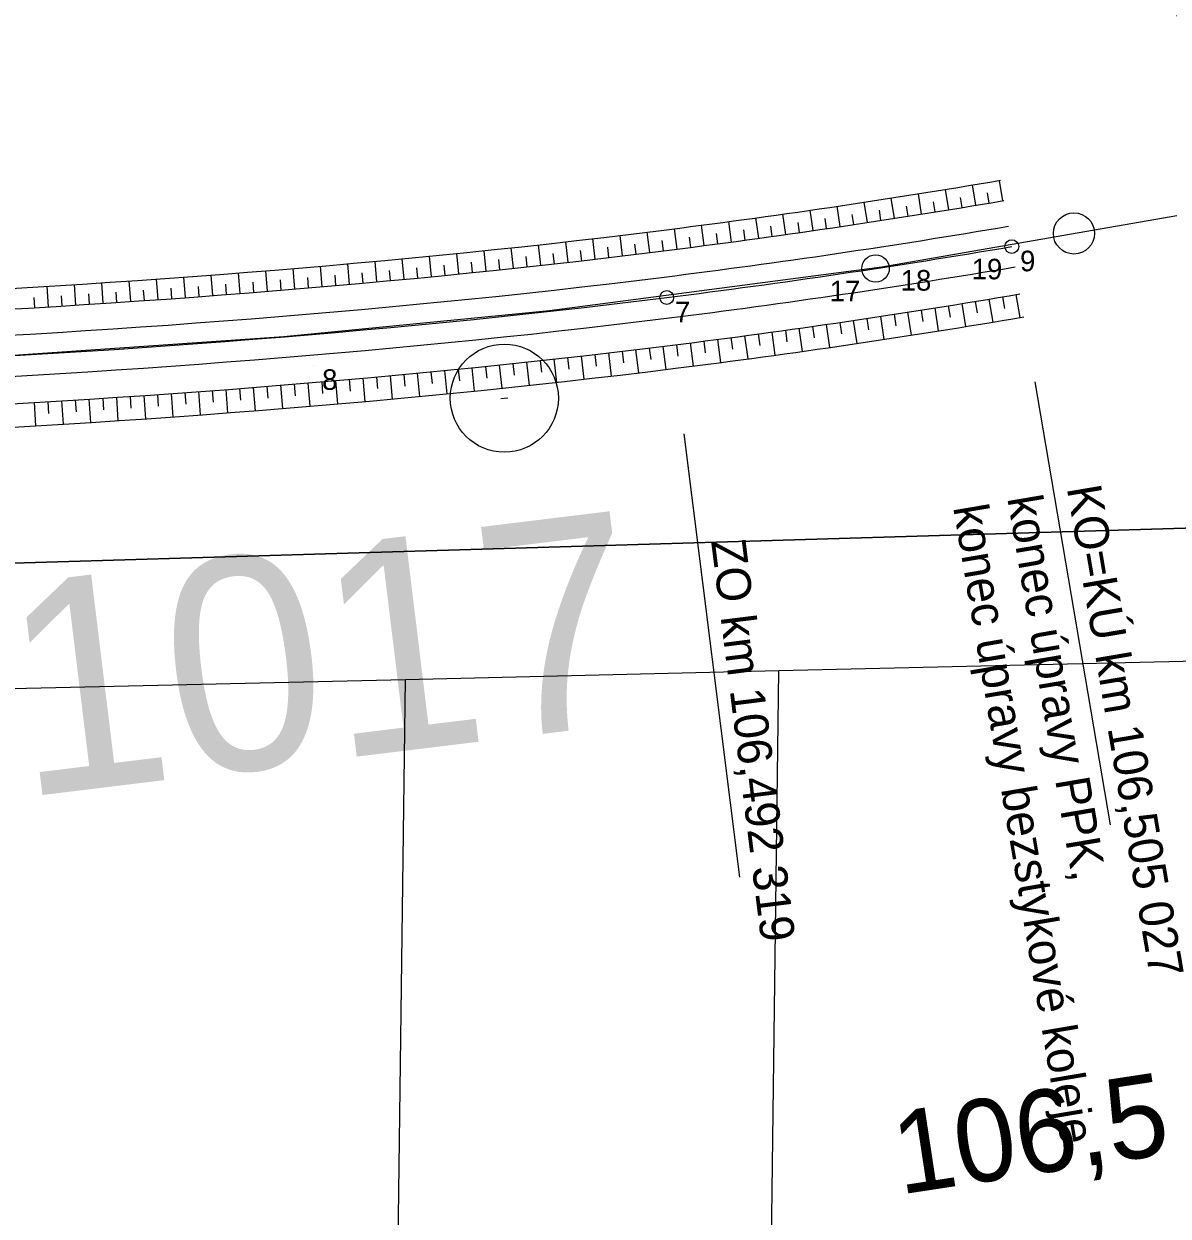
# Model space of a CAD drawing. Extents: x -758836 to -757729, y -1175316 to -1174366.
# Drawn here: x -758139.87 to -758098.18, y -1174793.97 to -1174750.54 of the extents above; entities that cross this region are included whole.
import ezdxf

# ---------------------------------------------------------------- set-up
doc = ezdxf.new("R2010")
doc.units = 0
for name, color, linetype in [('_NOR-návrh tenká', 7, 'Continuous'), ('_NOR-osa', 7, 'Continuous'), ('_NOR-popis', 7, 'Continuous'), ('_NOR-svahy', 7, 'Continuous'), ('_NOR-vytyčení', 7, 'Continuous'), ('G_Obvod stavby', 7, 'Continuous'), ('Hranice parcel', 7, 'Continuous'), ('Vrstva 1', 7, 'Continuous'), ('Vrstva 63', 7, 'Continuous'), ('Vrstva 7', 7, 'Continuous')]:
    doc.layers.add(name, color=color, linetype=linetype)

# ---------------------------------------------------------------- blocks, each defined once
blk = doc.blocks.new('C513_1')
at = {"layer": 'Vrstva 7'}
blk.add_circle((0, 0), 0.75, dxfattribs=at)
blk = doc.blocks.new('POINT_DISPLAY')
blk.add_line((0, 0), (0, 0))
blk = doc.blocks.new('C015_1')
at = {"layer": 'Vrstva 63'}
blk.add_line((-0.05, 0), (0.05, 0), dxfattribs=at)
blk.add_circle((0, 0), 0.756, dxfattribs=at)

msp = doc.modelspace()

# ---------------------------------------------------------------- linework, layer by layer
at = {"layer": '_NOR-návrh tenká'}
for points in [[(-758140.749, -1174760.203), (-758139.746, -1174760.144), (-758138.742, -1174760.083), (-758137.739, -1174760.02), (-758136.736, -1174759.955), (-758135.733, -1174759.887), (-758134.731, -1174759.816), (-758133.729, -1174759.744), (-758132.727, -1174759.669), (-758131.726, -1174759.591), (-758130.725, -1174759.51), (-758129.724, -1174759.427), (-758128.724, -1174759.341), (-758127.724, -1174759.253), (-758126.724, -1174759.161), (-758125.725, -1174759.067), (-758124.727, -1174758.97), (-758123.728, -1174758.869), (-758122.731, -1174758.766), (-758121.733, -1174758.66), (-758120.736, -1174758.55), (-758119.74, -1174758.437), (-758118.744, -1174758.321), (-758117.749, -1174758.201), (-758116.752, -1174758.078)], [(-758140.706, -1174760.952), (-758139.701, -1174760.893), (-758138.696, -1174760.832), (-758137.691, -1174760.768), (-758136.686, -1174760.703), (-758135.682, -1174760.635), (-758134.678, -1174760.565), (-758133.674, -1174760.492), (-758132.67, -1174760.416), (-758131.667, -1174760.338), (-758130.664, -1174760.258), (-758129.661, -1174760.175), (-758128.659, -1174760.089), (-758127.657, -1174760), (-758126.655, -1174759.908), (-758125.654, -1174759.814), (-758124.653, -1174759.716), (-758123.652, -1174759.616), (-758122.652, -1174759.512), (-758121.652, -1174759.405), (-758120.653, -1174759.295), (-758119.654, -1174759.182), (-758118.656, -1174759.066), (-758117.658, -1174758.946), (-758116.659, -1174758.823)], [(-758140.652, -1174761.9), (-758139.644, -1174761.841), (-758138.637, -1174761.78), (-758137.63, -1174761.716), (-758136.623, -1174761.651), (-758135.616, -1174761.583), (-758134.61, -1174761.512), (-758133.604, -1174761.439), (-758132.598, -1174761.364), (-758131.592, -1174761.285), (-758130.586, -1174761.205), (-758129.581, -1174761.121), (-758128.576, -1174761.035), (-758127.571, -1174760.946), (-758126.567, -1174760.854), (-758125.563, -1174760.759), (-758124.559, -1174760.661), (-758123.556, -1174760.561), (-758122.553, -1174760.457), (-758121.55, -1174760.35), (-758120.548, -1174760.239), (-758119.546, -1174760.126), (-758118.544, -1174760.009), (-758117.543, -1174759.889), (-758116.542, -1174759.765)], [(-758140.566, -1174763.398), (-758139.555, -1174763.338), (-758138.544, -1174763.277), (-758137.534, -1174763.213), (-758136.524, -1174763.147), (-758135.513, -1174763.079), (-758134.503, -1174763.008), (-758133.493, -1174762.935), (-758132.483, -1174762.859), (-758131.474, -1174762.781), (-758130.464, -1174762.7), (-758129.455, -1174762.616), (-758128.446, -1174762.529), (-758127.437, -1174762.44), (-758126.428, -1174762.348), (-758125.42, -1174762.252), (-758124.411, -1174762.154), (-758123.404, -1174762.053), (-758122.396, -1174761.949), (-758121.388, -1174761.841), (-758120.381, -1174761.73), (-758119.375, -1174761.616), (-758118.368, -1174761.499), (-758117.362, -1174761.378), (-758116.357, -1174761.254)], [(-758140.508, -1174764.396), (-758139.496, -1174764.337), (-758138.483, -1174764.275), (-758137.47, -1174764.211), (-758136.457, -1174764.145), (-758135.445, -1174764.077), (-758134.432, -1174764.006), (-758133.42, -1174763.932), (-758132.407, -1174763.856), (-758131.395, -1174763.778), (-758130.383, -1174763.696), (-758129.371, -1174763.612), (-758128.359, -1174763.526), (-758127.347, -1174763.436), (-758126.336, -1174763.343), (-758125.324, -1174763.248), (-758124.313, -1174763.149), (-758123.302, -1174763.048), (-758122.291, -1174762.943), (-758121.281, -1174762.835), (-758120.27, -1174762.724), (-758119.26, -1174762.61), (-758118.251, -1174762.492), (-758117.241, -1174762.371), (-758116.233, -1174762.246)], [(-758140.46, -1174765.245), (-758139.445, -1174765.185), (-758138.43, -1174765.124), (-758137.416, -1174765.06), (-758136.401, -1174764.993), (-758135.386, -1174764.925), (-758134.372, -1174764.854), (-758133.357, -1174764.78), (-758132.343, -1174764.704), (-758131.328, -1174764.625), (-758130.314, -1174764.544), (-758129.299, -1174764.459), (-758128.285, -1174764.372), (-758127.271, -1174764.283), (-758126.257, -1174764.19), (-758125.243, -1174764.094), (-758124.229, -1174763.995), (-758123.216, -1174763.893), (-758122.202, -1174763.788), (-758121.189, -1174763.68), (-758120.176, -1174763.569), (-758119.163, -1174763.454), (-758118.151, -1174763.336), (-758117.138, -1174763.214), (-758116.129, -1174763.09)]]:
    msp.add_lwpolyline(points, dxfattribs=at)
for radius, start in [(288.55, 277.14072), (289.3, 277.14059), (290.25, 277.14043), (291.75, 277.14018), (292.75, 277.14001), (293.6, 277.13986)]:
    msp.add_arc((-758152.621, -1174471.766), radius, start, 279.64253, dxfattribs=at)
at = {"layer": '_NOR-osa'}
msp.add_lwpolyline([(-758140.609, -1174762.649), (-758139.6, -1174762.59), (-758138.591, -1174762.528), (-758137.582, -1174762.465), (-758136.573, -1174762.399), (-758135.565, -1174762.331), (-758134.557, -1174762.26), (-758133.549, -1174762.187), (-758132.541, -1174762.111), (-758131.533, -1174762.033), (-758130.525, -1174761.952), (-758129.518, -1174761.869), (-758128.511, -1174761.782), (-758127.504, -1174761.693), (-758126.498, -1174761.601), (-758125.491, -1174761.506), (-758124.485, -1174761.408), (-758123.48, -1174761.307), (-758122.474, -1174761.203), (-758121.469, -1174761.095), (-758120.465, -1174760.985), (-758119.46, -1174760.871), (-758118.456, -1174760.754), (-758117.453, -1174760.633), (-758116.45, -1174760.51)], dxfattribs=at)
for centre in [(-758103.878, -1174758.655), (-758116.45, -1174760.51)]:
    msp.add_circle(centre, 0.25, dxfattribs=at)
msp.add_arc((-758152.621, -1174471.766), 291, 277.1403, 279.64253, dxfattribs=at)
at = {"layer": '_NOR-popis'}
for p, q in [((-758103.04, -1174763.584), (-758100.3, -1174779.715)), ((-758115.828, -1174765.471), (-758113.804, -1174781.63))]:
    msp.add_line(p, q, dxfattribs=at)
msp.add_circle((-758108.841, -1174759.454), 0.5, dxfattribs=at)
at = {"layer": '_NOR-svahy'}
for points in [[(-758105.19, -1174757.152), (-758105.313, -1174756.412)], [(-758104.204, -1174756.986), (-758104.33, -1174756.247)], [(-758108.152, -1174757.628), (-758108.268, -1174756.887)], [(-758107.164, -1174757.473), (-758107.282, -1174756.732)], [(-758106.177, -1174757.314), (-758106.298, -1174756.574)], [(-758105.684, -1174757.233), (-758105.745, -1174756.863)], [(-758104.697, -1174757.069), (-758104.759, -1174756.7)], [(-758111.119, -1174758.074), (-758111.227, -1174757.332)], [(-758110.13, -1174757.929), (-758110.24, -1174757.187)], [(-758109.141, -1174757.78), (-758109.253, -1174757.039)], [(-758108.646, -1174757.705), (-758108.703, -1174757.334)], [(-758107.658, -1174757.551), (-758107.717, -1174757.181)], [(-758106.671, -1174757.394), (-758106.73, -1174757.024)], [(-758114.09, -1174758.489), (-758114.19, -1174757.746)], [(-758113.099, -1174758.354), (-758113.202, -1174757.611)], [(-758112.109, -1174758.216), (-758112.214, -1174757.473)], [(-758111.614, -1174758.145), (-758111.667, -1174757.774)], [(-758110.624, -1174758.002), (-758110.679, -1174757.631)], [(-758109.635, -1174757.855), (-758109.691, -1174757.484)], [(-758117.066, -1174758.873), (-758117.157, -1174758.128)], [(-758116.073, -1174758.749), (-758116.168, -1174758.005)], [(-758115.081, -1174758.62), (-758115.179, -1174757.877)], [(-758114.586, -1174758.555), (-758114.635, -1174758.183)], [(-758113.595, -1174758.422), (-758113.645, -1174758.05)], [(-758112.604, -1174758.285), (-758112.656, -1174757.914)], [(-758121.038, -1174759.338), (-758121.12, -1174758.592)], [(-758120.045, -1174759.226), (-758120.129, -1174758.481)], [(-758119.051, -1174759.112), (-758119.138, -1174758.367)], [(-758118.058, -1174758.994), (-758118.148, -1174758.249)], [(-758117.562, -1174758.934), (-758117.608, -1174758.562)], [(-758116.569, -1174758.811), (-758116.616, -1174758.439)], [(-758115.577, -1174758.685), (-758115.625, -1174758.313)], [(-758126.012, -1174759.847), (-758126.083, -1174759.101)], [(-758125.017, -1174759.752), (-758125.09, -1174759.005)], [(-758124.022, -1174759.653), (-758124.097, -1174758.906)], [(-758123.027, -1174759.551), (-758123.104, -1174758.805)], [(-758122.033, -1174759.446), (-758122.112, -1174758.7)], [(-758121.535, -1174759.392), (-758121.576, -1174759.02)], [(-758120.541, -1174759.283), (-758120.584, -1174758.91)], [(-758119.548, -1174759.17), (-758119.591, -1174758.797)], [(-758118.555, -1174759.054), (-758118.599, -1174758.681)], [(-758130.993, -1174760.284), (-758131.053, -1174759.537)], [(-758129.996, -1174760.202), (-758130.059, -1174759.455)], [(-758129, -1174760.118), (-758129.064, -1174759.371)], [(-758128.004, -1174760.031), (-758128.07, -1174759.284)], [(-758127.008, -1174759.94), (-758127.076, -1174759.194)], [(-758126.51, -1174759.894), (-758126.545, -1174759.521)], [(-758125.515, -1174759.8), (-758125.551, -1174759.427)], [(-758124.519, -1174759.703), (-758124.557, -1174759.33)], [(-758123.524, -1174759.602), (-758123.563, -1174759.229)], [(-758122.53, -1174759.499), (-758122.569, -1174759.126)], [(-758136.977, -1174760.722), (-758137.026, -1174759.973)], [(-758135.979, -1174760.655), (-758136.03, -1174759.907)], [(-758134.982, -1174760.586), (-758135.034, -1174759.838)], [(-758133.984, -1174760.514), (-758134.039, -1174759.766)], [(-758132.987, -1174760.44), (-758133.043, -1174759.692)], [(-758131.99, -1174760.364), (-758132.048, -1174759.616)], [(-758131.491, -1174760.324), (-758131.522, -1174759.951)], [(-758130.495, -1174760.244), (-758130.526, -1174759.87)], [(-758129.498, -1174760.161), (-758129.53, -1174759.787)], [(-758128.502, -1174760.075), (-758128.535, -1174759.701)], [(-758127.506, -1174759.986), (-758127.54, -1174759.613)], [(-758138.973, -1174760.849), (-758139.018, -1174760.1)], [(-758137.975, -1174760.786), (-758138.022, -1174760.038)], [(-758137.476, -1174760.754), (-758137.5, -1174760.38)], [(-758136.478, -1174760.689), (-758136.503, -1174760.315)], [(-758135.48, -1174760.621), (-758135.507, -1174760.247)], [(-758134.483, -1174760.55), (-758134.51, -1174760.176)], [(-758133.486, -1174760.478), (-758133.514, -1174760.104)], [(-758132.488, -1174760.402), (-758132.517, -1174760.028)], [(-758103.728, -1174760.405), (-758103.586, -1174761.243)], [(-758139.472, -1174760.879), (-758139.495, -1174760.505)], [(-758138.474, -1174760.818), (-758138.498, -1174760.444)], [(-758106.194, -1174760.812), (-758106.127, -1174761.231)], [(-758105.701, -1174760.732), (-758105.564, -1174761.571)], [(-758105.207, -1174760.651), (-758105.138, -1174761.071)], [(-758104.714, -1174760.57), (-758104.575, -1174761.408)], [(-758104.221, -1174760.488), (-758104.15, -1174760.907)], [(-758109.159, -1174761.272), (-758109.096, -1174761.692)], [(-758108.664, -1174761.197), (-758108.537, -1174762.038)], [(-758108.17, -1174761.122), (-758108.106, -1174761.542)], [(-758107.676, -1174761.046), (-758107.545, -1174761.886)], [(-758107.182, -1174760.968), (-758107.116, -1174761.388)], [(-758106.688, -1174760.89), (-758106.555, -1174761.73)], [(-758112.128, -1174761.702), (-758112.069, -1174762.123)], [(-758111.633, -1174761.633), (-758111.514, -1174762.474)], [(-758111.138, -1174761.562), (-758111.077, -1174761.983)], [(-758110.643, -1174761.491), (-758110.521, -1174762.332)], [(-758110.148, -1174761.419), (-758110.086, -1174761.839)], [(-758109.653, -1174761.346), (-758109.528, -1174762.187)], [(-758115.101, -1174762.102), (-758115.046, -1174762.524)], [(-758114.605, -1174762.038), (-758114.495, -1174762.88)], [(-758114.109, -1174761.972), (-758114.053, -1174762.393)], [(-758113.614, -1174761.906), (-758113.501, -1174762.748)], [(-758113.118, -1174761.839), (-758113.061, -1174762.26)], [(-758112.623, -1174761.771), (-758112.507, -1174762.613)], [(-758118.575, -1174762.53), (-758118.476, -1174763.374)], [(-758118.078, -1174762.471), (-758118.027, -1174762.893)], [(-758117.582, -1174762.411), (-758117.48, -1174763.255)], [(-758117.085, -1174762.351), (-758117.033, -1174762.773)], [(-758116.589, -1174762.29), (-758116.485, -1174763.134)], [(-758116.093, -1174762.229), (-758116.04, -1174762.65)], [(-758115.597, -1174762.166), (-758115.489, -1174763.009)], [(-758122.55, -1174762.97), (-758122.463, -1174763.815)], [(-758122.053, -1174762.918), (-758122.008, -1174763.34)], [(-758121.556, -1174762.865), (-758121.466, -1174763.71)], [(-758121.059, -1174762.811), (-758121.012, -1174763.233)], [(-758120.562, -1174762.756), (-758120.469, -1174763.601)], [(-758120.065, -1174762.701), (-758120.017, -1174763.123)], [(-758119.568, -1174762.644), (-758119.472, -1174763.489)], [(-758119.071, -1174762.588), (-758119.022, -1174763.01)], [(-758127.527, -1174763.452), (-758127.452, -1174764.299)], [(-758127.029, -1174763.407), (-758126.99, -1174763.83)], [(-758126.531, -1174763.361), (-758126.454, -1174764.208)], [(-758126.033, -1174763.315), (-758125.993, -1174763.738)], [(-758125.536, -1174763.268), (-758125.456, -1174764.114)], [(-758125.038, -1174763.22), (-758124.997, -1174763.643)], [(-758124.54, -1174763.171), (-758124.458, -1174764.017)], [(-758124.043, -1174763.122), (-758124, -1174763.545)], [(-758123.545, -1174763.072), (-758123.46, -1174763.918)], [(-758123.048, -1174763.021), (-758123.004, -1174763.444)], [(-758132.51, -1174763.864), (-758132.446, -1174764.712)], [(-758132.011, -1174763.826), (-758131.979, -1174764.249)], [(-758131.513, -1174763.787), (-758131.447, -1174764.634)], [(-758131.015, -1174763.747), (-758130.98, -1174764.171)], [(-758130.516, -1174763.707), (-758130.448, -1174764.554)], [(-758130.018, -1174763.666), (-758129.983, -1174764.09)], [(-758129.52, -1174763.625), (-758129.449, -1174764.472)], [(-758129.021, -1174763.582), (-758128.985, -1174764.006)], [(-758128.523, -1174763.54), (-758128.45, -1174764.387)], [(-758128.025, -1174763.496), (-758127.988, -1174763.919)], [(-758138.995, -1174764.306), (-758138.969, -1174764.73)], [(-758138.496, -1174764.276), (-758138.444, -1174765.124)], [(-758137.997, -1174764.245), (-758137.97, -1174764.669)], [(-758137.498, -1174764.213), (-758137.444, -1174765.061)], [(-758136.999, -1174764.181), (-758136.971, -1174764.605)], [(-758136.5, -1174764.148), (-758136.444, -1174764.996)], [(-758136.001, -1174764.114), (-758135.972, -1174764.538)], [(-758135.502, -1174764.081), (-758135.445, -1174764.929)], [(-758135.003, -1174764.046), (-758134.974, -1174764.47)], [(-758134.505, -1174764.011), (-758134.445, -1174764.859)], [(-758134.006, -1174763.975), (-758133.975, -1174764.399)], [(-758133.507, -1174763.939), (-758133.446, -1174764.786)], [(-758133.009, -1174763.901), (-758132.977, -1174764.325)], [(-758139.494, -1174764.337), (-758139.442, -1174765.185)]]:
    msp.add_lwpolyline(points, dxfattribs=at)
at = {"layer": 'G_Obvod stavby'}
msp.add_lwpolyline([(-758392.72, -1174840.756), (-758391.23, -1174838.56), (-758368.37, -1174821.64), (-758340.31, -1174807.33), (-758320.27, -1174796.89), (-758301, -1174790.21), (-758267.96, -1174782.93), (-758224.96, -1174775.27), (-758184.87, -1174772.83), (-758142.71, -1174770.26), (-758089.84, -1174768.68), (-758106.02, -1174731.44), (-758149.09, -1174725.67), (-758199.62, -1174726.6), (-758225.76, -1174732.36), (-758252.17, -1174738.18), (-758254.97, -1174739.34), (-758266.58, -1174744.16), (-758279.45, -1174749.49), (-758302.42, -1174759.02), (-758331.68, -1174770.24), (-758367.17, -1174799.81), (-758405.64, -1174832.2)], dxfattribs=at)
at = {"layer": 'Hranice parcel'}
for p, q in [((-758125.97, -1174774.42), (-758112.36, -1174774.1)), ((-758114.13, -1174910.8), (-758112.36, -1174774.1)), ((-758141.37, -1174774.78), (-758125.97, -1174774.42)), ((-758127.73, -1174911.25), (-758125.97, -1174774.42))]:
    msp.add_line(p, q, dxfattribs=at)
for points in [[(-757877.73, -1174631.24), (-757883.07, -1174637.8), (-757892.39, -1174640.95), (-757964.85, -1174709.42), (-757976.05, -1174741.17), (-757981.89, -1174745.86), (-757990.29, -1174747.68), (-757997.69, -1174745.08), (-758004.14, -1174738), (-758040.32, -1174755.99), (-758089.84, -1174768.68), (-758142.71, -1174770.26), (-758184.87, -1174772.83)], [(-758112.36, -1174774.1), (-758087.64, -1174773.53), (-758083.84, -1174772.54)]]:
    msp.add_lwpolyline(points, dxfattribs=at)
at = {"layer": 'Vrstva 1'}
msp.add_lwpolyline([(-758275.047, -1174773.289), (-758265.484, -1174771.118), (-758253.61, -1174768.888), (-758243.69, -1174767.426), (-758231.371, -1174766.042), (-758219.363, -1174765.122), (-758206.915, -1174764.505), (-758194.225, -1174764.118), (-758182.013, -1174763.871), (-758170.862, -1174763.683), (-758162.019, -1174763.496), (-758153.195, -1174763.228), (-758152.069, -1174763.19), (-758141.836, -1174762.716), (-758130.402, -1174761.933), (-758120.726, -1174760.981), (-758108.612, -1174759.398), (-758096.467, -1174757.277), (-758085.591, -1174754.917)], dxfattribs=at)

# ---------------------------------------------------------------- block references
at = {"layer": '_NOR-vytyčení'}
for p in [(-758103.878, -1174758.655), (-758105.639, -1174758.949), (-758108.225, -1174759.36), (-758110.814, -1174759.748), (-758116.45, -1174760.51), (-758129.305, -1174762.975)]:
    msp.add_blockref('POINT_DISPLAY', p, dxfattribs=at)
at = {"layer": 'Vrstva 63', "xscale": 2.604378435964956, "yscale": 2.604378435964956, "rotation": 5.61911886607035}
msp.add_blockref('C015_1', (-758122.366, -1174764.177), dxfattribs=at)
at = {"layer": 'Vrstva 7', "rotation": 9.906217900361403}
msp.add_blockref('C513_1', (-758101.614, -1174758.176), dxfattribs=at)

# ---------------------------------------------------------------- texts
at = {"layer": '_NOR-popis'}
for s, height, rotation, p in [('konec úpravy PPK,', 1.25, 279.6425, (-758104.046, -1174767.813)), ('KO=KÚ km 106,505 027', 1.25, 279.6425, (-758101.878, -1174767.444)), ('konec úpravy bezstykové koleje', 1.25, 279.6425, (-758106.018, -1174768.148)), ('ZO km 106,492 319', 1.25, 277.1403, (-758114.835, -1174769.378)), ('106,5', 3, 8.6527, (-758107.951, -1174793.189))]:
    msp.add_text(s, height=height, rotation=rotation, dxfattribs=at).set_placement(p)
at = {"layer": '_NOR-vytyčení'}
for s, p in [('19', (-758105.339, -1174759.849)), ('9', (-758103.578, -1174759.555)), ('18', (-758107.925, -1174760.26)), ('17', (-758110.514, -1174760.648)), ('7', (-758116.15, -1174761.41)), ('8', (-758129.005, -1174763.875))]:
    msp.add_text(s, height=0.75, rotation=360, dxfattribs=at).set_placement(p)
at = {"layer": 'Vrstva 63'}
msp.add_text('1017', height=7.7553, rotation=6.9611, dxfattribs=at).set_placement((-758139.977, -1174778.728))

doc.saveas('drawing.dxf')
